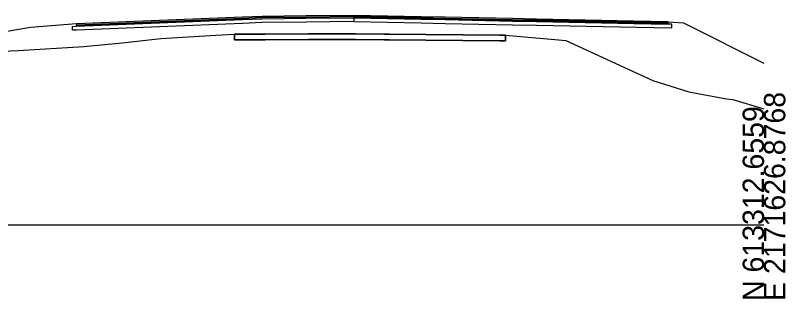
# Model space of a CAD drawing. Extents: x -26 to 1303, y -3010 to 12038.
# Drawn here: x 201.7 to 302.8, y 2990.3 to 3027.5 of the extents above; entities that cross this region are included whole.
import ezdxf

# ---------------------------------------------------------------- set-up
doc = ezdxf.new("R2010")
doc.units = 0
for name, color, linetype in [('RD_GPK_XS_Cell', 7, 'Continuous'), ('RD_XS_Base', 7, 'Continuous'), ('RD_XS_ExGround', 7, 'Continuous'), ('RD_XS_ExPaveRet', 7, 'Continuous'), ('RD_XS_Greenside', 7, 'Continuous'), ('RD_XS_Pave', 7, 'Continuous'), ('RD_XS_PaveOvlay_CP', 7, 'Continuous'), ('RD_XS_TieSlope', 7, 'Continuous')]:
    doc.layers.add(name, color=color, linetype=linetype)

msp = doc.modelspace()

# ---------------------------------------------------------------- linework, layer by layer
at = {"layer": 'RD_GPK_XS_Cell'}
msp.add_line((150, 3000), (300, 3000), dxfattribs=at)
at = {"layer": 'RD_XS_Base'}
for p, q in [((239.86, 3027.17), (246.12, 3027.23)), ((246.12, 3027.27), (246.12, 3027.39)), ((246.12, 3027.39), (246.12, 3026.9)), ((246.12, 3027.23), (246.12, 3027.27)), ((254.99, 3027.05), (246.12, 3027.23)), ((246.12, 3027.23), (246.12, 3026.86)), ((209.7, 3026.12), (231.51, 3026.99)), ((231.51, 3026.49), (209.7, 3025.62)), ((231.51, 3026.99), (234.12, 3027.1)), ((234.12, 3026.6), (231.51, 3026.49)), ((234.12, 3027.1), (239.86, 3027.17)), ((239.86, 3026.67), (234.12, 3026.6)), ((246.12, 3026.73), (239.86, 3026.67)), ((246.12, 3026.9), (246.12, 3026.73)), ((246.12, 3026.86), (246.12, 3026.73)), ((246.12, 3026.73), (254.99, 3026.55)), ((258.12, 3026.99), (254.99, 3027.05)), ((254.99, 3026.55), (258.12, 3026.49)), ((266.99, 3026.81), (258.12, 3026.99)), ((258.12, 3026.49), (266.99, 3026.31)), ((270.12, 3026.75), (266.99, 3026.81)), ((266.99, 3026.31), (270.12, 3026.25)), ((282.91, 3026.5), (270.12, 3026.75)), ((270.12, 3026.25), (283.28, 3025.99)), ((287.42, 3026.41), (282.91, 3026.5)), ((287.79, 3026.4), (287.42, 3026.41)), ((287.92, 3026.4), (287.79, 3026.4)), ((287.92, 3026.03), (287.92, 3026.4)), ((209.2, 3026.1), (209.57, 3026.12)), ((209.2, 3025.97), (209.2, 3026.1)), ((209.2, 3025.6), (209.2, 3025.97)), ((209.57, 3025.62), (209.2, 3025.6)), ((209.57, 3026.12), (209.7, 3026.12)), ((209.7, 3025.62), (209.57, 3025.62)), ((283.28, 3025.99), (287.92, 3025.9)), ((287.92, 3025.9), (287.92, 3026.03))]:
    msp.add_line(p, q, dxfattribs=at)
at = {"layer": 'RD_XS_ExGround'}
msp.add_lwpolyline([(199.95, 3022.83), (202.04, 3022.94), (210.67, 3023.47), (215.73, 3023.96), (220.8, 3024.5), (224.39, 3024.71), (228.04, 3024.93), (230.48, 3025.07), (234.34, 3025.09), (240.17, 3025.11), (246.34, 3025.13), (250.8, 3025.09), (266.05, 3024.95), (272.04, 3024.44), (273.97, 3024.25), (277.8, 3022.5), (285.39, 3018.98), (286.94, 3018.5), (290.15, 3017.48), (295.08, 3016.57), (295.89, 3016.49), (300, 3015.25)], dxfattribs=at)
at = {"layer": 'RD_XS_ExPaveRet'}
for p, q in [((265.29, 3024.96), (250.8, 3025.09)), ((266.05, 3024.95), (265.29, 3024.96))]:
    msp.add_line(p, q, dxfattribs=at)
for points in [[(265.29, 3024.96), (266.05, 3024.95), (266.05, 3024.9), (266.05, 3024.2), (265.29, 3024.21), (250.8, 3024.34), (250.16, 3024.35), (246.34, 3024.38), (241.06, 3024.36), (240.17, 3024.36), (234.49, 3024.34), (234.34, 3024.34), (230.58, 3024.32), (230.48, 3024.32), (230.48, 3024.32), (230.48, 3024.32), (230.48, 3025.02), (230.48, 3025.07), (230.48, 3025.07), (230.48, 3025.07), (230.58, 3025.07), (234.34, 3025.09), (234.49, 3025.09), (240.17, 3025.11), (241.06, 3025.11), (246.34, 3025.13), (250.16, 3025.1), (250.8, 3025.09), (265.29, 3024.96)], [(230.58, 3025.07), (230.48, 3025.07), (230.48, 3025.07), (230.48, 3025.02), (230.48, 3024.32), (230.48, 3024.32), (230.58, 3024.32), (234.34, 3024.34), (234.49, 3024.34), (240.17, 3024.36), (241.06, 3024.36), (246.34, 3024.38), (250.16, 3024.35), (250.8, 3024.34), (265.29, 3024.21), (266.05, 3024.2), (266.05, 3024.9), (266.05, 3024.95)], [(234.49, 3025.09), (234.34, 3025.09), (230.58, 3025.07)], [(246.34, 3025.13), (241.06, 3025.11), (240.17, 3025.11), (234.49, 3025.09)], [(250.8, 3025.09), (250.16, 3025.1), (246.34, 3025.13)]]:
    msp.add_lwpolyline(points, dxfattribs=at)
at = {"layer": 'RD_XS_Greenside'}
for p, q in [((289.42, 3026.56), (300, 3021.27)), ((203.7, 3025.96), (197.18, 3024.87))]:
    msp.add_line(p, q, dxfattribs=at)
at = {"layer": 'RD_XS_Pave'}
for p, q in [((231.51, 3027.31), (209.7, 3026.44)), ((234.12, 3027.42), (231.51, 3027.31)), ((234.12, 3027.26), (231.51, 3027.15)), ((231.51, 3027.15), (234.12, 3027.26)), ((239.86, 3027.48), (234.12, 3027.42)), ((239.86, 3027.33), (234.12, 3027.26)), ((234.12, 3027.26), (239.86, 3027.33)), ((246.12, 3027.55), (239.86, 3027.48)), ((246.12, 3027.39), (239.86, 3027.33)), ((239.86, 3027.33), (246.12, 3027.39)), ((239.86, 3027.17), (246.12, 3027.23)), ((254.99, 3027.37), (246.12, 3027.55)), ((246.12, 3027.27), (246.12, 3027.39)), ((246.12, 3027.39), (254.99, 3027.21)), ((254.99, 3027.21), (246.12, 3027.39)), ((246.12, 3027.39), (246.12, 3027.27)), ((246.12, 3027.23), (246.12, 3027.27)), ((246.12, 3027.27), (246.12, 3027.23)), ((246.12, 3027.23), (254.99, 3027.05)), ((258.12, 3027.31), (254.99, 3027.37)), ((254.99, 3027.21), (258.12, 3027.15)), ((258.12, 3027.15), (254.99, 3027.21)), ((266.99, 3027.13), (258.12, 3027.31)), ((231.51, 3027.15), (209.7, 3026.28)), ((209.7, 3026.28), (231.51, 3027.15)), ((209.7, 3026.12), (231.51, 3026.99)), ((209.7, 3026.44), (209.7, 3026.4)), ((209.7, 3026.4), (209.7, 3026.28)), ((209.7, 3026.28), (209.7, 3026.24)), ((209.7, 3026.24), (209.7, 3026.12)), ((231.51, 3026.99), (234.12, 3027.1)), ((234.12, 3027.1), (239.86, 3027.17)), ((254.99, 3027.05), (258.12, 3026.99)), ((258.12, 3027.15), (266.99, 3026.97)), ((266.99, 3026.97), (258.12, 3027.15)), ((258.12, 3026.99), (266.99, 3026.81)), ((270.12, 3027.07), (266.99, 3027.13)), ((266.99, 3026.97), (270.12, 3026.91)), ((270.12, 3026.91), (266.99, 3026.97)), ((266.99, 3026.81), (270.12, 3026.75)), ((282.91, 3026.81), (270.12, 3027.07)), ((270.12, 3026.91), (282.91, 3026.65)), ((282.91, 3026.65), (270.12, 3026.91)), ((270.12, 3026.75), (282.91, 3026.5)), ((287.42, 3026.72), (282.91, 3026.81)), ((282.91, 3026.65), (287.42, 3026.56)), ((287.42, 3026.56), (282.91, 3026.65)), ((282.91, 3026.5), (287.42, 3026.41)), ((287.42, 3026.61), (287.42, 3026.72)), ((287.42, 3026.56), (287.42, 3026.61)), ((287.42, 3026.45), (287.42, 3026.56)), ((287.42, 3026.41), (287.42, 3026.45))]:
    msp.add_line(p, q, dxfattribs=at)
at = {"layer": 'RD_XS_PaveOvlay_CP'}
for p, q in [((231.51, 3027.31), (209.7, 3026.44)), ((234.12, 3027.42), (231.51, 3027.31)), ((239.86, 3027.48), (234.12, 3027.42)), ((246.12, 3027.55), (239.86, 3027.48)), ((254.99, 3027.37), (246.12, 3027.55)), ((258.12, 3027.31), (254.99, 3027.37)), ((266.99, 3027.13), (258.12, 3027.31)), ((270.12, 3027.07), (266.99, 3027.13)), ((282.91, 3026.81), (270.12, 3027.07)), ((287.42, 3026.72), (282.91, 3026.81))]:
    msp.add_line(p, q, dxfattribs=at)
at = {"layer": 'RD_XS_TieSlope'}
for p, q in [((209.7, 3026.44), (203.7, 3025.96)), ((287.42, 3026.72), (289.42, 3026.56))]:
    msp.add_line(p, q, dxfattribs=at)

# ---------------------------------------------------------------- texts
at = {"layer": 'RD_GPK_XS_Cell'}
for s, p in [('E 2171626.8768', (302.8, 2990)), ('N 613312.6559', (300, 2990))]:
    msp.add_text(s, height=2.8, rotation=90, dxfattribs=at).set_placement(p)

doc.saveas('drawing.dxf')
